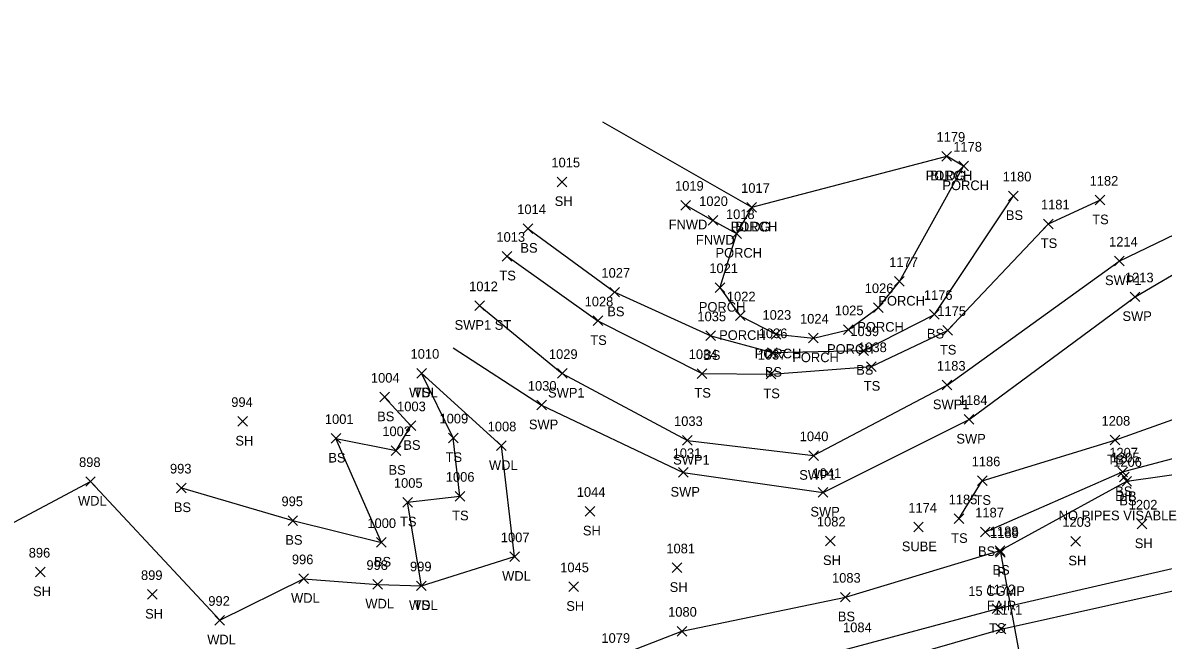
# Model space of a CAD drawing. Extents: x 1586965 to 1590952, y 716317 to 720029.
# Drawn here: x 1587407.7 to 1587644.2, y 719836.9 to 719964.8 of the extents above; entities that cross this region are included whole.
import ezdxf

# ---------------------------------------------------------------- set-up
doc = ezdxf.new("R2010")
doc.units = 0
for name, color, linetype in [('D_A', 7, 'Continuous'), ('D_C', 7, 'Continuous'), ('D_I', 7, 'Continuous'), ('D_TIC', 7, 'Continuous'), ('DCP', 7, 'Continuous'), ('L_A', 7, 'Continuous'), ('L_I', 7, 'Continuous'), ('L_TIC', 7, 'Continuous'), ('LAWA', 7, 'Continuous'), ('LBC', 7, 'Continuous'), ('LBF', 7, 'Continuous'), ('LELB', 7, 'Continuous'), ('LFNC', 7, 'Continuous'), ('P_I', 7, 'Continuous'), ('P_TIC', 7, 'Continuous'), ('PET', 7, 'Continuous'), ('R_A', 7, 'Continuous'), ('R_I', 7, 'Continuous'), ('R_TIC', 7, 'Continuous'), ('RSW', 7, 'Continuous'), ('U_A', 7, 'Continuous'), ('U_I', 7, 'Continuous'), ('U_TIC', 7, 'Continuous')]:
    doc.layers.add(name, color=color, linetype=linetype)

msp = doc.modelspace()

# ---------------------------------------------------------------- linework, layer by layer
at = {"layer": 'D_TIC'}
for points in [[(1587635.11, 719869.72), (1587637.11, 719871.72)], [(1587637.11, 719869.72), (1587635.11, 719871.72)], [(1587609.43, 719854.04), (1587611.43, 719856.04)], [(1587611.43, 719854.04), (1587609.43, 719856.04)]]:
    msp.add_lwpolyline(points, dxfattribs=at)
at = {"layer": 'DCP'}
msp.add_lwpolyline([(1587610.43, 719855.04), (1587620.04, 719803.24)], dxfattribs=at)
at = {"layer": 'L_TIC'}
for points in [[(1587598.31, 719936.19), (1587600.31, 719938.19)], [(1587600.31, 719936.19), (1587598.31, 719938.19)], [(1587598.31, 719936.19), (1587600.31, 719938.19)], [(1587600.31, 719936.19), (1587598.31, 719938.19)], [(1587601.79, 719934.16), (1587603.79, 719936.16)], [(1587603.79, 719934.16), (1587601.79, 719936.16)], [(1587518.53, 719930.88), (1587520.53, 719932.88)], [(1587520.53, 719930.88), (1587518.53, 719932.88)], [(1587612.12, 719927.97), (1587614.12, 719929.97)], [(1587614.12, 719927.97), (1587612.12, 719929.97)], [(1587630.06, 719927.09), (1587632.06, 719929.09)], [(1587632.06, 719927.09), (1587630.06, 719929.09)], [(1587544.18, 719926.04), (1587546.18, 719928.04)], [(1587546.18, 719926.04), (1587544.18, 719928.04)], [(1587557.88, 719925.6), (1587559.88, 719927.6)], [(1587559.88, 719925.6), (1587557.88, 719927.6)], [(1587557.88, 719925.6), (1587559.88, 719927.6)], [(1587559.88, 719925.6), (1587557.88, 719927.6)], [(1587549.83, 719922.87), (1587551.83, 719924.87)], [(1587551.83, 719922.87), (1587549.83, 719924.87)], [(1587619.4, 719922.17), (1587621.4, 719924.17)], [(1587621.4, 719922.17), (1587619.4, 719924.17)], [(1587511.45, 719921.19), (1587513.45, 719923.19)], [(1587513.45, 719921.19), (1587511.45, 719923.19)], [(1587554.73, 719920.16), (1587556.73, 719922.16)], [(1587556.73, 719920.16), (1587554.73, 719922.16)], [(1587507.13, 719915.45), (1587509.13, 719917.45)], [(1587509.13, 719915.45), (1587507.13, 719917.45)], [(1587588.5, 719910.23), (1587590.5, 719912.23)], [(1587590.5, 719910.23), (1587588.5, 719912.23)], [(1587529.47, 719908.01), (1587531.47, 719910.01)], [(1587531.47, 719908.01), (1587529.47, 719910.01)], [(1587551.28, 719908.96), (1587553.28, 719910.96)], [(1587553.28, 719908.96), (1587551.28, 719910.96)], [(1587555.48, 719903.11), (1587557.48, 719905.11)], [(1587557.48, 719903.11), (1587555.48, 719905.11)], [(1587584.13, 719904.82), (1587586.13, 719906.82)], [(1587586.13, 719904.82), (1587584.13, 719906.82)], [(1587595.74, 719903.41), (1587597.74, 719905.41)], [(1587597.74, 719903.41), (1587595.74, 719905.41)], [(1587525.98, 719902.07), (1587527.98, 719904.07)], [(1587527.98, 719902.07), (1587525.98, 719904.07)], [(1587549.37, 719898.98), (1587551.37, 719900.98)], [(1587551.37, 719898.98), (1587549.37, 719900.98)], [(1587562.87, 719899.29), (1587564.87, 719901.29)], [(1587564.87, 719899.29), (1587562.87, 719901.29)], [(1587570.65, 719898.5), (1587572.65, 719900.5)], [(1587572.65, 719898.5), (1587570.65, 719900.5)], [(1587577.87, 719900.23), (1587579.87, 719902.23)], [(1587579.87, 719900.23), (1587577.87, 719902.23)], [(1587598.48, 719900.08), (1587600.48, 719902.08)], [(1587600.48, 719900.08), (1587598.48, 719902.08)], [(1587562.14, 719895.48), (1587564.14, 719897.48)], [(1587564.14, 719895.48), (1587562.14, 719897.48)], [(1587581.09, 719895.9), (1587583.09, 719897.9)], [(1587583.09, 719895.9), (1587581.09, 719897.9)], [(1587489.41, 719891.21), (1587491.41, 719893.21)], [(1587491.41, 719891.21), (1587489.41, 719893.21)], [(1587489.41, 719891.21), (1587491.41, 719893.21)], [(1587491.41, 719891.21), (1587489.41, 719893.21)], [(1587582.69, 719892.58), (1587584.69, 719894.58)], [(1587584.69, 719892.58), (1587582.69, 719894.58)], [(1587547.57, 719891.14), (1587549.57, 719893.14)], [(1587549.57, 719891.14), (1587547.57, 719893.14)], [(1587561.87, 719891.03), (1587563.87, 719893.03)], [(1587563.87, 719891.03), (1587561.87, 719893.03)], [(1587481.75, 719886.25), (1587483.75, 719888.25)], [(1587483.75, 719886.25), (1587481.75, 719888.25)], [(1587452.3, 719881.22), (1587454.3, 719883.22)], [(1587454.3, 719881.22), (1587452.3, 719883.22)], [(1587487.18, 719880.32), (1587489.18, 719882.32)], [(1587489.18, 719880.32), (1587487.18, 719882.32)], [(1587471.63, 719877.69), (1587473.63, 719879.69)], [(1587473.63, 719877.69), (1587471.63, 719879.69)], [(1587495.98, 719877.8), (1587497.98, 719879.8)], [(1587497.98, 719877.8), (1587495.98, 719879.8)], [(1587633.17, 719877.33), (1587635.17, 719879.33)], [(1587635.17, 719877.33), (1587633.17, 719879.33)], [(1587484.11, 719875.16), (1587486.11, 719877.16)], [(1587486.11, 719875.16), (1587484.11, 719877.16)], [(1587505.96, 719876.16), (1587507.96, 719878.16)], [(1587507.96, 719876.16), (1587505.96, 719878.16)], [(1587634.78, 719870.74), (1587636.78, 719872.74)], [(1587636.78, 719870.74), (1587634.78, 719872.74)], [(1587420.75, 719868.76), (1587422.75, 719870.76)], [(1587422.75, 719868.76), (1587420.75, 719870.76)], [(1587605.66, 719868.92), (1587607.66, 719870.92)], [(1587607.66, 719868.92), (1587605.66, 719870.92)], [(1587635.65, 719868.8), (1587637.65, 719870.8)], [(1587637.65, 719868.8), (1587635.65, 719870.8)], [(1587439.59, 719867.42), (1587441.59, 719869.42)], [(1587441.59, 719867.42), (1587439.59, 719869.42)], [(1587497.34, 719865.71), (1587499.34, 719867.71)], [(1587499.34, 719865.71), (1587497.34, 719867.71)], [(1587486.52, 719864.45), (1587488.52, 719866.45)], [(1587488.52, 719864.45), (1587486.52, 719866.45)], [(1587462.71, 719860.65), (1587464.71, 719862.65)], [(1587464.71, 719860.65), (1587462.71, 719862.65)], [(1587524.36, 719862.58), (1587526.36, 719864.58)], [(1587526.36, 719862.58), (1587524.36, 719864.58)], [(1587600.82, 719861.03), (1587602.82, 719863.03)], [(1587602.82, 719861.03), (1587600.82, 719863.03)], [(1587606.33, 719858.31), (1587608.33, 719860.31)], [(1587608.33, 719858.31), (1587606.33, 719860.31)], [(1587638.81, 719859.95), (1587640.81, 719861.95)], [(1587640.81, 719859.95), (1587638.81, 719861.95)], [(1587481.09, 719856.12), (1587483.09, 719858.12)], [(1587483.09, 719856.12), (1587481.09, 719858.12)], [(1587574.16, 719856.44), (1587576.16, 719858.44)], [(1587576.16, 719856.44), (1587574.16, 719858.44)], [(1587625.04, 719856.37), (1587627.04, 719858.37)], [(1587627.04, 719856.37), (1587625.04, 719858.37)], [(1587609.35, 719854.43), (1587611.35, 719856.43)], [(1587611.35, 719854.43), (1587609.35, 719856.43)], [(1587508.69, 719853.18), (1587510.69, 719855.18)], [(1587510.69, 719853.18), (1587508.69, 719855.18)], [(1587410.36, 719849.99), (1587412.36, 719851.99)], [(1587412.36, 719849.99), (1587410.36, 719851.99)], [(1587542.36, 719850.87), (1587544.36, 719852.87)], [(1587544.36, 719850.87), (1587542.36, 719852.87)], [(1587464.93, 719848.61), (1587466.93, 719850.61)], [(1587466.93, 719848.61), (1587464.93, 719850.61)], [(1587480.33, 719847.44), (1587482.33, 719849.44)], [(1587482.33, 719847.44), (1587480.33, 719849.44)], [(1587489.38, 719847.13), (1587491.38, 719849.13)], [(1587491.38, 719847.13), (1587489.38, 719849.13)], [(1587489.38, 719847.13), (1587491.38, 719849.13)], [(1587491.38, 719847.13), (1587489.38, 719849.13)], [(1587520.93, 719846.95), (1587522.93, 719848.95)], [(1587522.93, 719846.95), (1587520.93, 719848.95)], [(1587433.59, 719845.34), (1587435.59, 719847.34)], [(1587435.59, 719845.34), (1587433.59, 719847.34)], [(1587577.28, 719844.78), (1587579.28, 719846.78)], [(1587579.28, 719844.78), (1587577.28, 719846.78)], [(1587608.69, 719842.39), (1587610.69, 719844.39)], [(1587610.69, 719842.39), (1587608.69, 719844.39)], [(1587447.54, 719839.99), (1587449.54, 719841.99)], [(1587449.54, 719839.99), (1587447.54, 719841.99)], [(1587543.39, 719837.73), (1587545.39, 719839.73)], [(1587545.39, 719837.73), (1587543.39, 719839.73)]]:
    msp.add_lwpolyline(points, dxfattribs=at)
at = {"layer": 'LAWA'}
msp.add_lwpolyline([(1587310.49, 719797.97), (1587303.6, 719782.03), (1587310.05, 719774.45), (1587323.07, 719768.88), (1587335.99, 719770.75), (1587348.78, 719777.46), (1587367.57, 719816.19), (1587376.29, 719846.67), (1587402.77, 719859.66), (1587421.75, 719869.76), (1587448.54, 719840.99), (1587465.93, 719849.61), (1587481.33, 719848.44), (1587490.38, 719848.13), (1587509.69, 719854.18), (1587506.96, 719877.16), (1587490.41, 719892.21)], dxfattribs=at)
at = {"layer": 'LBC'}
msp.add_lwpolyline([(1587527.94, 719944.35), (1587558.88, 719926.6), (1587599.31, 719937.19)], dxfattribs=at)
at = {"layer": 'LBF'}
msp.add_lwpolyline([(1587558.88, 719926.6), (1587555.73, 719921.16), (1587552.28, 719909.96), (1587556.48, 719904.11), (1587563.87, 719900.29), (1587571.65, 719899.5), (1587578.87, 719901.23), (1587585.13, 719905.82), (1587589.5, 719911.23), (1587602.79, 719935.16), (1587599.31, 719937.19)], dxfattribs=at)
at = {"layer": 'LELB'}
for points in [[(1587348.34, 719750.32), (1587376.14, 719764.57), (1587411.23, 719784.15), (1587458.35, 719804.18), (1587473.61, 719812.83), (1587489.06, 719812.38), (1587530.46, 719833.31), (1587544.39, 719838.73), (1587578.28, 719845.78), (1587610.35, 719855.43), (1587636.65, 719869.8), (1587651.78, 719871.98), (1587673.75, 719879.3), (1587684.98, 719885.25), (1587696.5, 719901.07), (1587712.21, 719917.3), (1587727.23, 719932.21), (1587743.8, 719944.38), (1587761.72, 719949.74)], [(1587348.34, 719750.32), (1587376.14, 719764.57), (1587411.23, 719784.15), (1587458.35, 719804.18), (1587473.61, 719812.83), (1587489.06, 719812.38), (1587530.46, 719833.31), (1587544.39, 719838.73), (1587578.28, 719845.78), (1587610.35, 719855.43), (1587636.65, 719869.8), (1587651.78, 719871.98), (1587673.75, 719879.3), (1587684.98, 719885.25), (1587696.5, 719901.07), (1587712.21, 719917.3), (1587727.23, 719932.21), (1587743.8, 719944.38), (1587761.72, 719949.74)], [(1587377.37, 719757.84), (1587414.05, 719779.22), (1587461.92, 719797.99), (1587490.32, 719809.23), (1587530.45, 719822.09), (1587580.58, 719835.52), (1587609.69, 719843.39), (1587653.83, 719853.5), (1587683.02, 719862.16), (1587697.57, 719874.31), (1587709.76, 719884.81), (1587725.71, 719899.33), (1587733.52, 719907.93), (1587757.13, 719931.09), (1587771.49, 719945.87)], [(1587377.37, 719757.84), (1587414.05, 719779.22), (1587461.92, 719797.99), (1587490.32, 719809.23), (1587530.45, 719822.09), (1587580.58, 719835.52), (1587609.69, 719843.39), (1587653.83, 719853.5), (1587683.02, 719862.16), (1587697.57, 719874.31), (1587709.76, 719884.81), (1587725.71, 719899.33), (1587733.52, 719907.93), (1587757.13, 719931.09), (1587771.49, 719945.87)], [(1587601.82, 719862.03), (1587606.66, 719869.92), (1587634.17, 719878.33), (1587648.32, 719883.38), (1587669.78, 719891.1), (1587679.24, 719892.79), (1587689.74, 719906.67), (1587697.67, 719925.84), (1587713.13, 719934.53)], [(1587601.82, 719862.03), (1587606.66, 719869.92), (1587634.17, 719878.33), (1587648.32, 719883.38), (1587669.78, 719891.1), (1587679.24, 719892.79), (1587689.74, 719906.67), (1587697.67, 719925.84), (1587713.13, 719934.53)], [(1587512.45, 719922.19), (1587530.47, 719909.01), (1587550.37, 719899.98), (1587563.14, 719896.48), (1587582.09, 719896.9), (1587596.74, 719904.41), (1587613.12, 719928.97)], [(1587512.45, 719922.19), (1587530.47, 719909.01), (1587550.37, 719899.98), (1587563.14, 719896.48), (1587582.09, 719896.9), (1587596.74, 719904.41), (1587613.12, 719928.97)], [(1587508.13, 719916.45), (1587526.98, 719903.07), (1587548.57, 719892.14), (1587562.87, 719892.03), (1587583.69, 719893.58), (1587599.48, 719901.08), (1587620.4, 719923.17), (1587631.06, 719928.09)], [(1587508.13, 719916.45), (1587526.98, 719903.07), (1587548.57, 719892.14), (1587562.87, 719892.03), (1587583.69, 719893.58), (1587599.48, 719901.08), (1587620.4, 719923.17), (1587631.06, 719928.09)], [(1587607.33, 719859.31), (1587635.78, 719871.74), (1587650.63, 719875.7), (1587672.46, 719882.75), (1587682.48, 719888.45), (1587694.28, 719903.42)], [(1587607.33, 719859.31), (1587635.78, 719871.74), (1587650.63, 719875.7), (1587672.46, 719882.75), (1587682.48, 719888.45), (1587694.28, 719903.42)], [(1587490.38, 719848.13), (1587487.52, 719865.45), (1587498.34, 719866.71), (1587496.98, 719878.8), (1587490.41, 719892.21)], [(1587490.38, 719848.13), (1587487.52, 719865.45), (1587498.34, 719866.71), (1587496.98, 719878.8), (1587490.41, 719892.21)], [(1587440.59, 719868.42), (1587463.71, 719861.65), (1587482.09, 719857.12), (1587472.63, 719878.69), (1587485.11, 719876.16), (1587488.18, 719881.32), (1587482.75, 719887.25)], [(1587440.59, 719868.42), (1587463.71, 719861.65), (1587482.09, 719857.12), (1587472.63, 719878.69), (1587485.11, 719876.16), (1587488.18, 719881.32), (1587482.75, 719887.25)]]:
    msp.add_lwpolyline(points, dxfattribs=at)
at = {"layer": 'LFNC'}
for points in [[(1587545.18, 719927.04), (1587550.83, 719923.87)], [(1587550.83, 719923.87), (1587555.73, 719921.16)]]:
    msp.add_lwpolyline(points, dxfattribs=at)
at = {"layer": 'P_TIC'}
for points in [[(1587609.56, 719838.15), (1587611.56, 719840.15)], [(1587611.56, 719838.15), (1587609.56, 719840.15)]]:
    msp.add_lwpolyline(points, dxfattribs=at)
at = {"layer": 'PET'}
msp.add_lwpolyline([(1587380.68, 719751.95), (1587418.28, 719771.56), (1587465.09, 719790.26), (1587493.56, 719801.4), (1587532.06, 719815.42), (1587581.77, 719830.86), (1587610.56, 719839.15), (1587655.26, 719849.11), (1587685.91, 719854.02), (1587717.2, 719859.97), (1587741.36, 719862.44), (1587760.59, 719863.49), (1587776.56, 719860.57), (1587795.98, 719858.74), (1587820.3, 719853.13)], dxfattribs=at)
at = {"layer": 'R_TIC'}
for points in [[(1587634.09, 719914.47), (1587636.09, 719916.47)], [(1587636.09, 719914.47), (1587634.09, 719916.47)], [(1587637.37, 719907.04), (1587639.37, 719909.04)], [(1587639.37, 719907.04), (1587637.37, 719909.04)], [(1587501.47, 719905.21), (1587503.47, 719907.21)], [(1587503.47, 719905.21), (1587501.47, 719907.21)], [(1587518.59, 719891.17), (1587520.59, 719893.17)], [(1587520.59, 719891.17), (1587518.59, 719893.17)], [(1587598.39, 719888.75), (1587600.39, 719890.75)], [(1587600.39, 719888.75), (1587598.39, 719890.75)], [(1587514.3, 719884.59), (1587516.3, 719886.59)], [(1587516.3, 719884.59), (1587514.3, 719886.59)], [(1587602.93, 719881.63), (1587604.93, 719883.63)], [(1587604.93, 719881.63), (1587602.93, 719883.63)], [(1587544.54, 719877.27), (1587546.54, 719879.27)], [(1587546.54, 719877.27), (1587544.54, 719879.27)], [(1587570.68, 719874.12), (1587572.68, 719876.12)], [(1587572.68, 719874.12), (1587570.68, 719876.12)], [(1587543.67, 719870.63), (1587545.67, 719872.63)], [(1587545.67, 719870.63), (1587543.67, 719872.63)], [(1587572.67, 719866.5), (1587574.67, 719868.5)], [(1587574.67, 719866.5), (1587572.67, 719868.5)]]:
    msp.add_lwpolyline(points, dxfattribs=at)
at = {"layer": 'RSW'}
for points in [[(1587502.47, 719906.21), (1587519.59, 719892.17), (1587545.54, 719878.27), (1587571.68, 719875.12), (1587599.39, 719889.75), (1587635.09, 719915.47), (1587660.31, 719927.61), (1587704.19, 719952.84), (1587746.6, 719964.48), (1587765.98, 719964.85), (1587774.31, 719963.73)], [(1587496.93, 719897.46), (1587515.3, 719885.59), (1587544.67, 719871.63), (1587573.67, 719867.5), (1587603.93, 719882.63), (1587638.37, 719908.04), (1587662.83, 719922.42), (1587707.8, 719945.74), (1587750.38, 719956.64), (1587766.18, 719956.72), (1587775.73, 719956.55)]]:
    msp.add_lwpolyline(points, dxfattribs=at)
at = {"layer": 'U_TIC'}
for points in [[(1587592.45, 719859.31), (1587594.45, 719861.31)], [(1587594.45, 719859.31), (1587592.45, 719861.31)]]:
    msp.add_lwpolyline(points, dxfattribs=at)

# ---------------------------------------------------------------- texts
at = {"layer": 'D_A'}
for s, p in [('DIB', (1587634.22, 719865.72)), ('P', (1587609.81, 719850.04))]:
    msp.add_text(s, height=2, dxfattribs=at).set_placement(p)
at = {"layer": 'D_C'}
for s, p in [('NO PIPES VISABLE', (1587622.52, 719861.72)), ('15 CGMP ', (1587603.77, 719846.04)), ('FAIR', (1587607.61, 719843.04))]:
    msp.add_text(s, height=2, dxfattribs=at).set_placement(p)
at = {"layer": 'D_I'}
for s, p in [('1205', (1587633.34, 719873.72)), ('1189', (1587608.3, 719858.04))]:
    msp.add_text(s, height=2, dxfattribs=at).set_placement(p)
at = {"layer": 'L_A'}
for s, p in [('PORCH', (1587594.93, 719932.19)), ('BLDG', (1587595.9, 719932.19)), ('PORCH', (1587598.41, 719930.16)), ('SH', (1587518.01, 719926.88)), ('FNWD', (1587541.64, 719922.04)), ('BS', (1587611.56, 719923.97)), ('TS', (1587629.47, 719923.09)), ('PORCH', (1587554.5, 719921.6)), ('BLDG', (1587555.47, 719921.6)), ('BS', (1587510.89, 719917.19)), ('FNWD', (1587547.29, 719918.87)), ('TS', (1587618.8, 719918.17)), ('PORCH', (1587551.35, 719916.16)), ('TS', (1587506.54, 719911.45)), ('PORCH', (1587585.12, 719906.23)), ('BS', (1587528.91, 719904.01)), ('PORCH', (1587547.9, 719904.96)), ('PORCH', (1587580.75, 719900.82)), ('PORCH', (1587552.11, 719899.11)), ('BS', (1587595.19, 719899.41)), ('TS', (1587525.39, 719898.07)), ('PORCH', (1587574.49, 719896.23)), ('TS', (1587597.89, 719896.08)), ('BS', (1587548.81, 719894.98)), ('PORCH', (1587559.49, 719895.29)), ('PORCH', (1587567.27, 719894.5)), ('BS', (1587561.58, 719891.48)), ('BS', (1587580.53, 719891.9)), ('WDL', (1587487.82, 719887.21)), ('TS', (1587488.82, 719887.21)), ('TS', (1587546.98, 719887.14)), ('TS', (1587561.28, 719887.03)), ('TS', (1587582.1, 719888.58)), ('BS', (1587481.19, 719882.25)), ('SH', (1587451.79, 719877.22)), ('BS', (1587486.62, 719876.32)), ('BS', (1587471.07, 719873.69)), ('TS', (1587495.39, 719873.8)), ('TS', (1587632.58, 719873.33)), ('BS', (1587483.55, 719871.16)), ('WDL', (1587504.38, 719872.16)), ('BS', (1587634.23, 719866.74)), ('WDL', (1587419.16, 719864.76)), ('BS', (1587439.03, 719863.42)), ('TS', (1587605.07, 719864.92)), ('BS', (1587635.09, 719864.8)), ('TS', (1587485.93, 719860.45)), ('TS', (1587496.75, 719861.71)), ('SH', (1587523.85, 719858.58)), ('BS', (1587462.15, 719856.65)), ('TS', (1587600.23, 719857.03)), ('SH', (1587638.3, 719855.95)), ('BS', (1587605.78, 719854.31)), ('BS', (1587480.53, 719852.12)), ('SH', (1587573.64, 719852.44)), ('SH', (1587624.53, 719852.37)), ('WDL', (1587507.11, 719849.18)), ('BS', (1587608.79, 719850.43)), ('SH', (1587541.85, 719846.87)), ('SH', (1587409.85, 719845.99)), ('WDL', (1587463.34, 719844.61)), ('WDL', (1587478.75, 719843.44)), ('WDL', (1587487.8, 719843.13)), ('TS', (1587488.79, 719843.13)), ('SH', (1587520.41, 719842.95)), ('SH', (1587433.08, 719841.34)), ('BS', (1587576.72, 719840.78)), ('TS', (1587608.1, 719838.39)), ('WDL', (1587445.96, 719835.99))]:
    msp.add_text(s, height=2, dxfattribs=at).set_placement(p)
at = {"layer": 'L_I'}
for s, p in [('1179', (1587597.18, 719940.19)), ('1179', (1587597.18, 719940.19)), ('1178', (1587600.66, 719938.16)), ('1015', (1587517.32, 719934.88)), ('1180', (1587610.91, 719931.97)), ('1019', (1587542.96, 719930.04)), ('1017', (1587556.67, 719929.6)), ('1017', (1587556.67, 719929.6)), ('1182', (1587628.93, 719931.09)), ('1020', (1587547.97, 719926.87)), ('1014', (1587510.24, 719925.19)), ('1181', (1587618.84, 719926.17)), ('1018', (1587553.52, 719924.16)), ('1013', (1587505.92, 719919.45)), ('1021', (1587550.07, 719912.96)), ('1177', (1587587.38, 719914.23)), ('1027', (1587527.7, 719912.01)), ('1026', (1587582.3, 719908.82)), ('1028', (1587524.21, 719906.07)), ('1022', (1587553.71, 719907.11)), ('1176', (1587594.56, 719907.41)), ('1023', (1587561.1, 719903.29)), ('1025', (1587576.1, 719904.23)), ('1175', (1587597.35, 719904.08)), ('1035', (1587547.6, 719902.98)), ('1024', (1587568.88, 719902.5)), ('1036', (1587560.31, 719899.48)), ('1039', (1587579.31, 719899.9)), ('1038', (1587580.92, 719896.58)), ('1010', (1587488.12, 719895.21)), ('1010', (1587488.12, 719895.21)), ('1034', (1587545.8, 719895.14)), ('1037', (1587560.1, 719895.03)), ('1004', (1587479.9, 719890.25)), ('994', (1587450.94, 719885.22)), ('1003', (1587485.33, 719884.32)), ('1009', (1587494.12, 719881.8)), ('1001', (1587470.35, 719881.69)), ('1008', (1587504.11, 719880.16)), ('1208', (1587631.4, 719881.33)), ('1002', (1587482.26, 719879.16)), ('1207', (1587633.01, 719874.74)), ('898', (1587419.38, 719872.76)), ('1186', (1587604.47, 719872.92)), ('1206', (1587633.82, 719872.8)), ('993', (1587438.23, 719871.42)), ('1005', (1587484.67, 719868.45)), ('1006', (1587495.43, 719869.71)), ('1044', (1587522.59, 719866.58)), ('995', (1587461.35, 719864.65)), ('1185', (1587599.7, 719865.03)), ('1202', (1587637.04, 719863.95)), ('1082', (1587572.38, 719860.44)), ('1187', (1587605.21, 719862.31)), ('1000', (1587479.16, 719860.12)), ('1188', (1587608.22, 719858.43)), ('1203', (1587623.27, 719860.37)), ('1007', (1587506.84, 719857.18)), ('896', (1587408.94, 719853.99)), ('1081', (1587541.16, 719854.87)), ('996', (1587463.51, 719852.61)), ('998', (1587478.97, 719851.44)), ('999', (1587488.01, 719851.13)), ('999', (1587488.01, 719851.13)), ('899', (1587432.22, 719849.34)), ('1045', (1587519.15, 719850.95)), ('1083', (1587575.51, 719848.78)), ('1172', (1587607.57, 719846.39)), ('992', (1587446.18, 719843.99)), ('1080', (1587541.53, 719841.73)), ('1084', (1587577.8, 719838.52)), ('1079', (1587527.69, 719836.31))]:
    msp.add_text(s, height=2, dxfattribs=at).set_placement(p)
at = {"layer": 'P_I'}
msp.add_text('1171', height=2, dxfattribs=at).set_placement((1587609, 719842.15))
at = {"layer": 'R_A'}
for s, p in [('SWP1', (1587632.13, 719910.47)), ('SWP', (1587635.74, 719903.04)), ('SWP1 ST', (1587497.25, 719901.21)), ('SWP1', (1587516.63, 719887.17)), ('SWP1', (1587596.43, 719884.75)), ('SWP', (1587512.66, 719880.59)), ('SWP', (1587601.3, 719877.63)), ('SWP1', (1587542.58, 719873.27)), ('SWP1', (1587568.72, 719870.12)), ('SWP', (1587542.03, 719866.63)), ('SWP', (1587571.04, 719862.5))]:
    msp.add_text(s, height=2, dxfattribs=at).set_placement(p)
at = {"layer": 'R_I'}
for s, p in [('1214', (1587632.97, 719918.47)), ('1213', (1587636.25, 719911.04)), ('1012', (1587500.27, 719909.21)), ('1029', (1587516.81, 719895.17)), ('1183', (1587597.26, 719892.75)), ('1030', (1587512.44, 719888.59)), ('1184', (1587601.81, 719885.63)), ('1033', (1587542.76, 719881.27)), ('1040', (1587568.82, 719878.12)), ('1031', (1587542.46, 719874.63)), ('1041', (1587571.47, 719870.5))]:
    msp.add_text(s, height=2, dxfattribs=at).set_placement(p)
at = {"layer": 'U_A'}
msp.add_text('SUBE', height=2, dxfattribs=at).set_placement((1587589.99, 719855.31))
at = {"layer": 'U_I'}
msp.add_text('1174', height=2, dxfattribs=at).set_placement((1587591.33, 719863.31))

doc.saveas('drawing.dxf')
